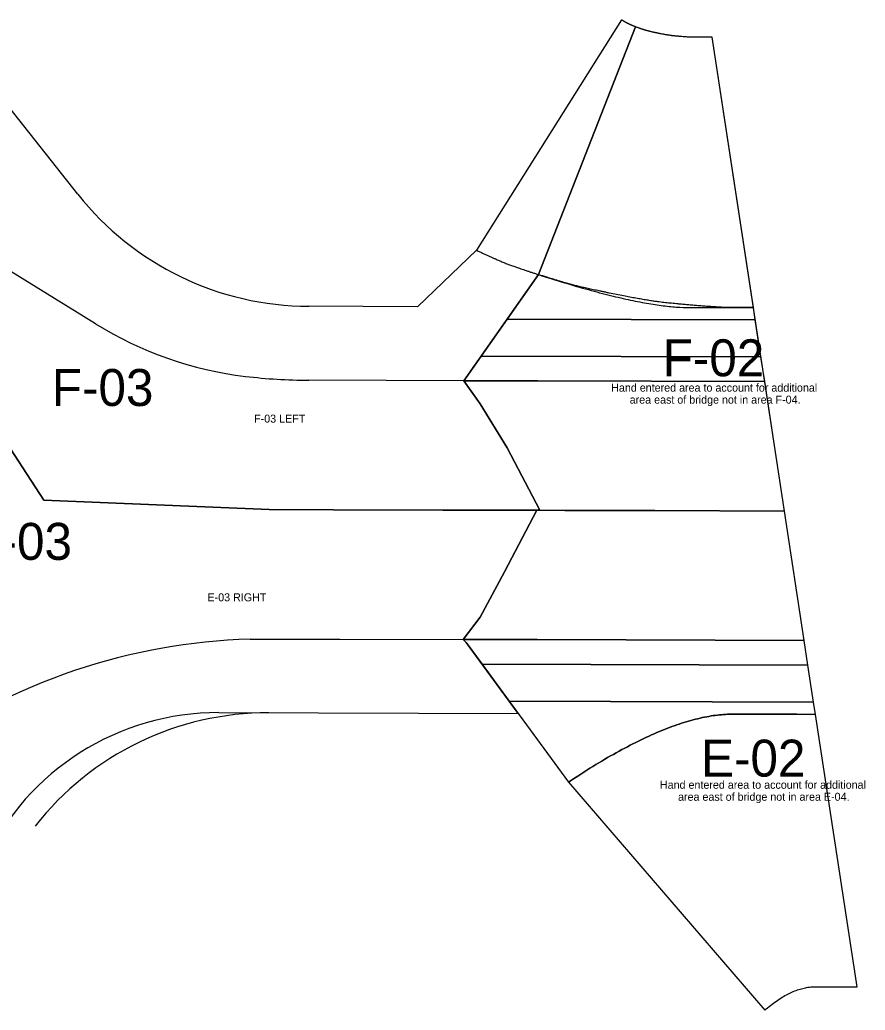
# Model space of a CAD drawing. Extents: x 5196716 to 5200291, y 3709146 to 3713154.
# Drawn here: x 5196983.8 to 5197121, y 3709269.7 to 3709430.4 of the extents above; entities that cross this region are included whole.
import ezdxf

# ---------------------------------------------------------------- set-up
doc = ezdxf.new("R2010")
doc.units = 0
for name, color, linetype in [('Drainage-Area', 7, 'Continuous'), ('dsnTextNote', 7, 'Continuous'), ('Level 1', 7, 'Continuous'), ('Level 2', 7, 'Continuous'), ('Level 3', 7, 'Continuous'), ('Level 4', 7, 'Continuous')]:
    doc.layers.add(name, color=color, linetype=linetype)

msp = doc.modelspace()

# ---------------------------------------------------------------- linework, layer by layer
at = {"layer": 'Drainage-Area'}
msp.add_line((5197072.89, 3709306.65), (5197104.73, 3709269.65), dxfattribs=at)
for points in [[(5197055.78, 3709329.84), (5197058.54, 3709333.45), (5197062.47, 3709340.79), (5197067.77, 3709350.81)], [(5197055.78, 3709329.84), (5197056.3, 3709329.37), (5197072.89, 3709306.65)]]:
    msp.add_lwpolyline(points, dxfattribs=at)
msp.add_arc((5197024.09, 3709269.93), 48, 89.8345, 141.9065, dxfattribs=at)
at = {"layer": 'Level 1'}
for p, q in [((5197081.48, 3709430.44), (5197057.96, 3709393.02)), ((5197083.77, 3709429.3), (5197068.04, 3709389.06)), ((5197068.04, 3709389.06), (5197083.77, 3709429.3)), ((5197096.2, 3709427.61), (5197093.16, 3709427.61)), ((5197106.21, 3709362.02), (5197096.2, 3709427.61)), ((5196993.25, 3709402.11), (5196974.62, 3709425.62)), ((5197057.96, 3709393.02), (5197048.39, 3709383.86)), ((5197068.04, 3709389.06), (5197055.9, 3709371.84)), ((5197055.9, 3709371.84), (5197068.04, 3709389.06)), ((5197048.39, 3709383.86), (5197030.74, 3709383.92)), ((5196987.74, 3709352.43), (5196980.1, 3709364.11)), ((5196980.1, 3709364.11), (5196987.74, 3709352.43)), ((5197107.94, 3709350.69), (5197106.21, 3709362.02)), ((5197024.32, 3709350.93), (5196987.74, 3709352.43)), ((5196987.74, 3709352.43), (5197024.32, 3709350.93)), ((5197034.74, 3709350.9), (5197024.32, 3709350.93)), ((5197024.32, 3709350.93), (5197034.74, 3709350.9)), ((5197052.46, 3709350.85), (5197034.74, 3709350.9)), ((5197034.74, 3709350.9), (5197052.46, 3709350.85)), ((5197056.33, 3709350.84), (5197052.46, 3709350.85)), ((5197052.46, 3709350.85), (5197055.46, 3709350.84)), ((5197055.46, 3709350.84), (5197056.33, 3709350.84)), ((5197067.77, 3709350.81), (5197056.33, 3709350.84)), ((5197056.33, 3709350.84), (5197057.15, 3709350.84)), ((5197057.15, 3709350.84), (5197068.23, 3709350.81)), ((5197086.88, 3709350.75), (5197067.77, 3709350.81)), ((5197107.94, 3709350.69), (5197086.88, 3709350.75)), ((5197086.88, 3709350.75), (5197107.94, 3709350.69)), ((5197112.99, 3709317.68), (5197112.68, 3709319.68)), ((5197112.99, 3709317.68), (5197112.68, 3709319.68)), ((5197016.13, 3709317.96), (5197064.73, 3709317.82)), ((5197119.74, 3709273.43), (5197112.99, 3709317.68)), ((5197119.74, 3709273.43), (5197112.99, 3709317.68)), ((5197072.89, 3709306.65), (5197104.73, 3709269.65)), ((5197116.71, 3709273.43), (5197119.74, 3709273.43))]:
    msp.add_line(p, q, dxfattribs=at)
for points in [[(5197055.9, 3709371.84), (5197058.56, 3709368.07), (5197062.94, 3709360.94), (5197068.23, 3709350.81)], [(5197068.23, 3709350.81), (5197062.94, 3709360.94), (5197058.56, 3709368.07), (5197055.9, 3709371.84)], [(5197067.77, 3709350.81), (5197062.47, 3709340.79), (5197058.54, 3709333.45), (5197055.78, 3709329.84)], [(5197055.78, 3709329.84), (5197058.54, 3709333.45), (5197062.47, 3709340.79), (5197067.77, 3709350.81)], [(5197068.23, 3709350.81), (5197072.29, 3709350.8), (5197076.88, 3709350.78), (5197086.88, 3709350.75)], [(5197112.68, 3709319.68), (5197111.76, 3709325.68), (5197111.15, 3709329.68), (5197107.94, 3709350.69)], [(5197112.68, 3709319.68), (5197111.76, 3709325.68), (5197111.15, 3709329.68), (5197107.94, 3709350.69)], [(5197055.78, 3709329.84), (5197056.3, 3709329.37), (5197072.89, 3709306.65)], [(5197064.73, 3709317.82), (5197056.3, 3709329.37), (5197055.78, 3709329.84)]]:
    msp.add_lwpolyline(points, dxfattribs=at)
for centre, radius, start, end in [((5197030.88, 3709431.92), 48, 218.3928, 269.8345), ((5197016.01, 3709276.13), 41.83, 89.8345, 154.8409)]:
    msp.add_arc(centre, radius, start, end, dxfattribs=at)
for points in [[(5197083.77, 3709429.3), (5197082.96, 3709429.62), (5197082.19, 3709429.99), (5197081.48, 3709430.44)], [(5197086.91, 3709428.36), (5197085.87, 3709428.6), (5197084.8, 3709428.9), (5197083.77, 3709429.3)], [(5197087.82, 3709428.17), (5197087.52, 3709428.23), (5197087.22, 3709428.29), (5197086.91, 3709428.36)], [(5197091.31, 3709427.7), (5197090.37, 3709427.78), (5197089.15, 3709427.92), (5197087.82, 3709428.17)], [(5197093.16, 3709427.61), (5197093.16, 3709427.61), (5197092.44, 3709427.61), (5197091.31, 3709427.7)], [(5197104.73, 3709269.65), (5197109.17, 3709273.47), (5197116.71, 3709273.43), (5197116.71, 3709273.43)]]:
    msp.add_open_spline(points, degree=2, dxfattribs=at)
at = {"layer": 'Level 2'}
for p, q in [((5196996.1, 3709381.08), (5196981.68, 3709390)), ((5197062.94, 3709381.82), (5197058.71, 3709375.84)), ((5197103.21, 3709381.71), (5197062.94, 3709381.82)), ((5197104.12, 3709375.7), (5197103.21, 3709381.71)), ((5197058.71, 3709375.84), (5197104.12, 3709375.7)), ((5197055.9, 3709371.84), (5197030.7, 3709371.92)), ((5197067.9, 3709371.81), (5197055.9, 3709371.84)), ((5197055.9, 3709371.84), (5197058.56, 3709368.07)), ((5197104.73, 3709371.7), (5197067.9, 3709371.81)), ((5197106.21, 3709362.02), (5197104.73, 3709371.7)), ((5197058.56, 3709368.07), (5197062.94, 3709360.94)), ((5196980.1, 3709364.11), (5196987.74, 3709352.43)), ((5196987.74, 3709352.43), (5196980.1, 3709364.11)), ((5197068.23, 3709350.81), (5197062.94, 3709360.94)), ((5197062.94, 3709360.94), (5197068.23, 3709350.81)), ((5197107.94, 3709350.69), (5197106.21, 3709362.02)), ((5196987.74, 3709352.43), (5197024.32, 3709350.93)), ((5197024.32, 3709350.93), (5196987.74, 3709352.43)), ((5197024.32, 3709350.93), (5197034.74, 3709350.9)), ((5197034.74, 3709350.9), (5197024.32, 3709350.93)), ((5197034.74, 3709350.9), (5197052.46, 3709350.85)), ((5197052.46, 3709350.85), (5197034.74, 3709350.9)), ((5197052.46, 3709350.85), (5197055.46, 3709350.84)), ((5197055.46, 3709350.84), (5197052.46, 3709350.85)), ((5197055.46, 3709350.84), (5197056.33, 3709350.84)), ((5197056.33, 3709350.84), (5197055.46, 3709350.84)), ((5197056.33, 3709350.84), (5197057.15, 3709350.84)), ((5197057.15, 3709350.84), (5197056.33, 3709350.84)), ((5197057.15, 3709350.84), (5197068.23, 3709350.81)), ((5197067.77, 3709350.81), (5197057.15, 3709350.84)), ((5197068.23, 3709350.81), (5197072.29, 3709350.8)), ((5197072.29, 3709350.8), (5197076.88, 3709350.78)), ((5197076.88, 3709350.78), (5197072.29, 3709350.8)), ((5197076.88, 3709350.78), (5197086.88, 3709350.75)), ((5197086.88, 3709350.75), (5197076.88, 3709350.78)), ((5197086.88, 3709350.75), (5197107.94, 3709350.69)), ((5197107.94, 3709350.69), (5197086.88, 3709350.75)), ((5197111.15, 3709329.68), (5197107.94, 3709350.69)), ((5197058.54, 3709333.45), (5197055.78, 3709329.84)), ((5197055.78, 3709329.84), (5197058.54, 3709333.45)), ((5197021.21, 3709329.9), (5197024.26, 3709329.9)), ((5197024.26, 3709329.9), (5197035.77, 3709329.9)), ((5197035.77, 3709329.9), (5197055.78, 3709329.84)), ((5197055.78, 3709329.84), (5197067.78, 3709329.81)), ((5197067.78, 3709329.81), (5197111.15, 3709329.68)), ((5197111.76, 3709325.68), (5197058.88, 3709325.83)), ((5197058.88, 3709325.83), (5197063.27, 3709319.82)), ((5197112.68, 3709319.68), (5197111.76, 3709325.68)), ((5197063.27, 3709319.82), (5197112.68, 3709319.68))]:
    msp.add_line(p, q, dxfattribs=at)
for points in [[(5197062.94, 3709360.94), (5197058.56, 3709368.07), (5197055.9, 3709371.84)], [(5197067.77, 3709350.81), (5197062.47, 3709340.79), (5197058.54, 3709333.45)], [(5197058.54, 3709333.45), (5197062.47, 3709340.79), (5197067.77, 3709350.81)], [(5197072.29, 3709350.8), (5197068.23, 3709350.81), (5197067.77, 3709350.81)]]:
    msp.add_lwpolyline(points, dxfattribs=at)
for centre, radius, start, end in [((5197027.66, 3709432.11), 60, 238.2692, 263.1077), ((5197030.96, 3709459.42), 87.5, 263.1077, 269.8345), ((5197023.98, 3709232.43), 97.5, 91.6298, 125.7719)]:
    msp.add_arc(centre, radius, start, end, dxfattribs=at)
at = {"layer": 'Level 3'}
for p, q in [((5197081.48, 3709430.44), (5197057.96, 3709393.02)), ((5197068.04, 3709389.06), (5197083.77, 3709429.3)), ((5197083.77, 3709429.3), (5197068.04, 3709389.06)), ((5197096.2, 3709427.61), (5197093.16, 3709427.61)), ((5197102.9, 3709383.71), (5197096.2, 3709427.61)), ((5197099.86, 3709383.72), (5197102.9, 3709383.71)), ((5197112.99, 3709317.68), (5197109.95, 3709317.69)), ((5197119.74, 3709273.43), (5197112.99, 3709317.68)), ((5197072.88, 3709306.66), (5197104.73, 3709269.65)), ((5197116.71, 3709273.43), (5197119.74, 3709273.43))]:
    msp.add_line(p, q, dxfattribs=at)
for points in [[(5197083.77, 3709429.3), (5197082.96, 3709429.62), (5197082.19, 3709429.99), (5197081.48, 3709430.44)], [(5197086.91, 3709428.36), (5197085.87, 3709428.6), (5197084.8, 3709428.9), (5197083.77, 3709429.3)], [(5197087.82, 3709428.17), (5197087.52, 3709428.23), (5197087.22, 3709428.29), (5197086.91, 3709428.36)], [(5197091.31, 3709427.7), (5197090.37, 3709427.78), (5197089.15, 3709427.92), (5197087.82, 3709428.17)], [(5197093.16, 3709427.61), (5197093.16, 3709427.61), (5197092.44, 3709427.61), (5197091.31, 3709427.7)], [(5197057.96, 3709393.02), (5197061.28, 3709391.45), (5197064.68, 3709390.15), (5197068.04, 3709389.06)], [(5197068.04, 3709389.06), (5197084.46, 3709383.76), (5197099.86, 3709383.72), (5197099.86, 3709383.72)], [(5197109.95, 3709317.69), (5197109.95, 3709317.69), (5197089.41, 3709317.75), (5197072.88, 3709306.66)], [(5197104.73, 3709269.65), (5197109.17, 3709273.47), (5197116.71, 3709273.43), (5197116.71, 3709273.43)]]:
    msp.add_open_spline(points, degree=2, dxfattribs=at)
at = {"layer": 'Level 4'}
for p, q in [((5197068.04, 3709389.06), (5197062.94, 3709381.82)), ((5197102.9, 3709383.71), (5197099.86, 3709383.72)), ((5197103.21, 3709381.71), (5197102.9, 3709383.71)), ((5197062.94, 3709381.82), (5197103.21, 3709381.71)), ((5197058.71, 3709375.84), (5197055.9, 3709371.84)), ((5197104.12, 3709375.7), (5197058.71, 3709375.84)), ((5197104.73, 3709371.7), (5197104.12, 3709375.7)), ((5197055.9, 3709371.84), (5197067.9, 3709371.81)), ((5197067.9, 3709371.81), (5197104.73, 3709371.7)), ((5197067.78, 3709329.81), (5197055.78, 3709329.84)), ((5197111.15, 3709329.68), (5197067.78, 3709329.81)), ((5197111.76, 3709325.68), (5197111.15, 3709329.68)), ((5197058.88, 3709325.83), (5197111.76, 3709325.68)), ((5197112.68, 3709319.68), (5197063.27, 3709319.82)), ((5197063.27, 3709319.82), (5197072.88, 3709306.66)), ((5197112.99, 3709317.68), (5197112.68, 3709319.68)), ((5197109.95, 3709317.69), (5197112.99, 3709317.68))]:
    msp.add_line(p, q, dxfattribs=at)
msp.add_lwpolyline([(5197055.78, 3709329.84), (5197056.3, 3709329.37), (5197058.88, 3709325.83)], dxfattribs=at)
for points in [[(5197079.49, 3709386.08), (5197075.86, 3709386.82), (5197071.98, 3709387.79), (5197068.04, 3709389.06)], [(5197094.57, 3709383.97), (5197090.88, 3709384.26), (5197085.54, 3709384.85), (5197079.49, 3709386.08)], [(5197099.86, 3709383.72), (5197099.86, 3709383.72), (5197097.88, 3709383.72), (5197094.57, 3709383.97)], [(5197072.88, 3709306.66), (5197089.41, 3709317.75), (5197109.95, 3709317.69), (5197109.95, 3709317.69)]]:
    msp.add_open_spline(points, degree=2, dxfattribs=at)

# ---------------------------------------------------------------- texts
at = {"layer": 'dsnTextNote'}
for s, height, p in [('F-02', 6, (5197088.17, 3709372.56)), ('F-03', 6, (5196989.01, 3709367.74)), ('Hand entered area to account for additional ', 1.3, (5197079.82, 3709370.07)), ('area east of bridge not in area F-04.', 1.3, (5197082.82, 3709368.12)), ('F-03 LEFT', 1.3, (5197021.85, 3709365.04)), ('E-03', 6, (5196975.34, 3709342.76)), ('E-03 RIGHT', 1.3, (5197014.28, 3709336.03)), ('E-02', 6, (5197094.4, 3709307.57)), ('Hand entered area to account for additional ', 1.3, (5197087.73, 3709305.6)), ('area east of bridge not in area E-04.', 1.3, (5197090.67, 3709303.65))]:
    msp.add_text(s, height=height, dxfattribs=at).set_placement(p)

doc.saveas('drawing.dxf')
